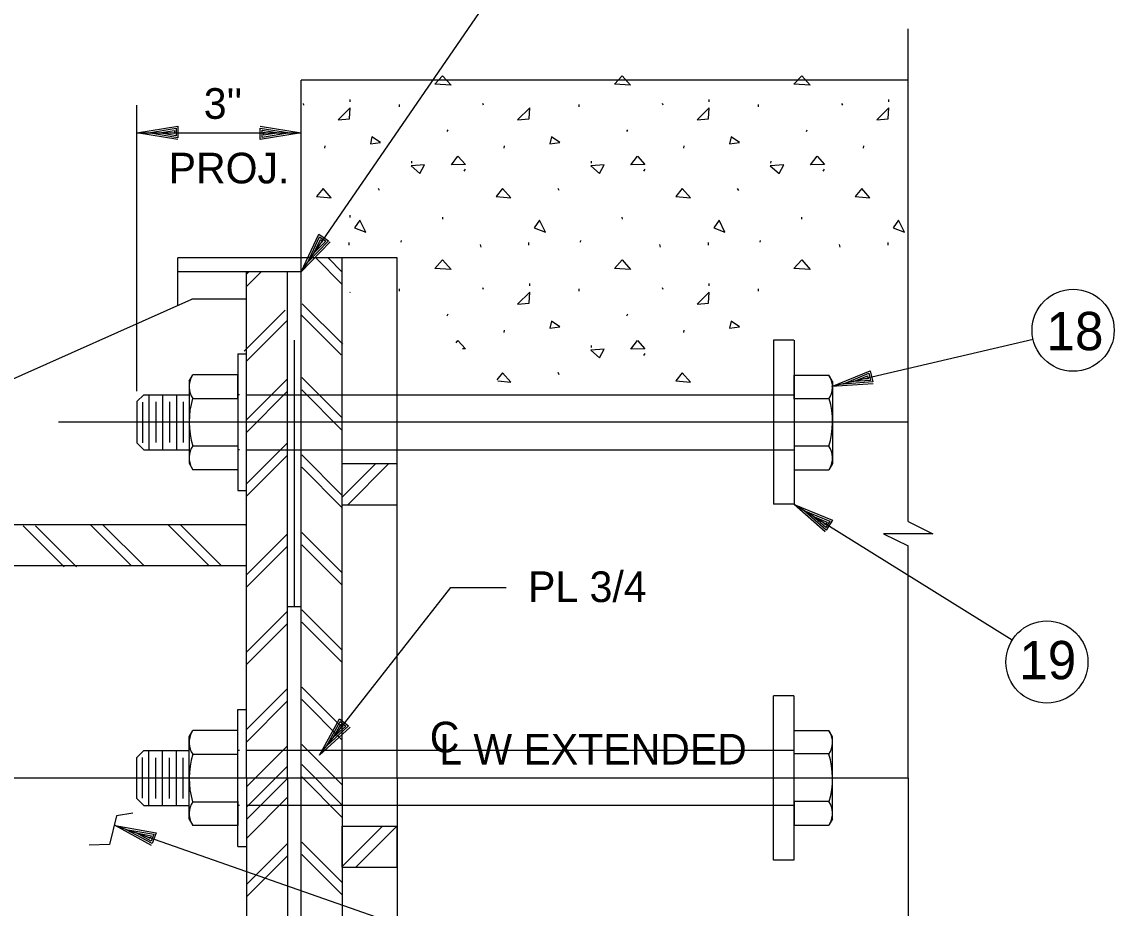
# Model space of a CAD drawing. Extents: x 0.1 to 13.5, y 0.1 to 9.5.
# Drawn here: x 8.756 to 10.418, y 6.836 to 8.186 of the extents above; entities that cross this region are included whole.
import ezdxf

# ---------------------------------------------------------------- set-up
doc = ezdxf.new("R2010")
doc.units = 0
for name, color, linetype in [('Level 10', 7, 'Continuous'), ('Level 13', 7, 'Continuous'), ('Level 2', 7, 'Continuous'), ('Level 25', 7, 'Continuous'), ('Level 3', 7, 'Continuous'), ('Level 50', 7, 'Continuous')]:
    doc.layers.add(name, color=color, linetype=linetype)

msp = doc.modelspace()

# ---------------------------------------------------------------- linework, layer by layer
at = {"layer": 'Level 10'}
for p, q in [((9.2555, 8.064), (9.2555, 8.0675)), ((9.8022, 8.064), (9.8022, 8.0675)), ((10.0755, 8.064), (10.0755, 8.0675)), ((9.1852, 8.0585), (9.1842, 8.0612)), ((9.3307, 8.056), (9.3307, 8.0597)), ((9.4585, 8.0585), (9.4575, 8.0612)), ((9.604, 8.056), (9.604, 8.0597)), ((9.7318, 8.0585), (9.7308, 8.0612)), ((9.8773, 8.056), (9.8773, 8.0597)), ((10.0052, 8.0585), (10.0041, 8.0612)), ((9.4033, 8.0185), (9.4047, 8.0214)), ((9.6766, 8.0185), (9.678, 8.0214)), ((9.9499, 8.0185), (9.9513, 8.0214)), ((9.2167, 7.9933), (9.2173, 7.9969)), ((9.49, 7.9933), (9.4906, 7.9969)), ((9.7633, 7.9933), (9.7639, 7.9969)), ((10.0367, 7.9933), (10.0372, 7.9969)), ((9.3493, 7.9705), (9.3495, 7.9732)), ((9.6226, 7.9705), (9.6228, 7.9732)), ((9.8959, 7.9705), (9.8962, 7.9732)), ((9.4291, 7.958), (9.431, 7.9611)), ((9.7024, 7.958), (9.7043, 7.9611)), ((9.9757, 7.958), (9.9776, 7.9611)), ((9.3003, 7.9287), (9.2987, 7.932)), ((9.5737, 7.9287), (9.572, 7.932)), ((9.847, 7.9287), (9.8453, 7.932)), ((9.2555, 7.8876), (9.2555, 7.8911)), ((9.3966, 7.8852), (9.3963, 7.8882)), ((9.6699, 7.8852), (9.6697, 7.8882)), ((9.9432, 7.8852), (9.943, 7.8882)), ((9.2542, 7.8457), (9.2542, 7.8494)), ((9.333, 7.8501), (9.3335, 7.8529)), ((9.5275, 7.8457), (9.5275, 7.8494)), ((9.6063, 7.8501), (9.6068, 7.8529)), ((9.8008, 7.8457), (9.8008, 7.8494)), ((9.8797, 7.8501), (9.8802, 7.8529)), ((10.0742, 7.8457), (10.0742, 7.8494)), ((9.4548, 7.8427), (9.4537, 7.8464)), ((9.7281, 7.8427), (9.727, 7.8464)), ((10.0014, 7.8427), (10.0003, 7.8464)), ((9.5288, 7.7835), (9.5288, 7.787)), ((9.8022, 7.7835), (9.8022, 7.787)), ((9.3307, 7.7754), (9.3307, 7.7792)), ((9.4585, 7.778), (9.4575, 7.7807)), ((9.604, 7.7754), (9.604, 7.7792)), ((9.7318, 7.778), (9.7308, 7.7807)), ((9.8773, 7.7754), (9.8773, 7.7792)), ((9.4033, 7.7379), (9.4047, 7.7408)), ((9.6766, 7.7379), (9.678, 7.7408)), ((9.49, 7.7127), (9.4906, 7.7163)), ((9.7633, 7.7127), (9.7639, 7.7163)), ((9.6226, 7.6899), (9.6228, 7.6927)), ((9.7024, 7.6774), (9.7043, 7.6805)), ((9.5737, 7.6482), (9.572, 7.6515))]:
    msp.add_line(p, q, dxfattribs=at)
for points in [[(9.3843, 8.0907), (9.3962, 8.1035), (9.409, 8.0893)], [(9.6577, 8.0907), (9.6695, 8.1035), (9.6823, 8.0893)], [(9.931, 8.0907), (9.9428, 8.1035), (9.9556, 8.0893)], [(9.2546, 8.038), (9.2555, 8.0547), (9.237, 8.0366)], [(9.5279, 8.038), (9.5288, 8.0547), (9.5103, 8.0366)], [(9.8012, 8.038), (9.8022, 8.0547), (9.7837, 8.0366)], [(10.0745, 8.038), (10.0755, 8.0547), (10.057, 8.0366)], [(9.2863, 7.9998), (9.3015, 8.0018), (9.2887, 8.0103)], [(9.5596, 7.9998), (9.5748, 8.0018), (9.562, 8.0103)], [(9.8329, 7.9998), (9.8481, 8.0018), (9.8353, 8.0103)], [(9.3483, 7.9664), (9.3617, 7.9545), (9.3688, 7.9678)], [(9.4095, 7.9678), (9.4195, 7.9812), (9.4308, 7.9683)], [(9.6217, 7.9664), (9.635, 7.9545), (9.6421, 7.9678)], [(9.6828, 7.9678), (9.6928, 7.9812), (9.7042, 7.9683)], [(9.895, 7.9664), (9.9083, 7.9545), (9.9154, 7.9678)], [(9.9561, 7.9678), (9.9662, 7.9812), (9.9775, 7.9683)], [(9.2267, 7.9175), (9.2143, 7.9317), (9.2043, 7.9199)], [(9.5, 7.9175), (9.4876, 7.9317), (9.4777, 7.9199)], [(9.7733, 7.9175), (9.7609, 7.9317), (9.751, 7.9199)], [(10.0466, 7.9175), (10.0342, 7.9317), (10.0243, 7.9199)], [(9.2623, 7.8719), (9.2794, 7.8653), (9.2704, 7.8837)], [(9.5357, 7.8719), (9.5527, 7.8653), (9.5437, 7.8837)], [(9.809, 7.8719), (9.826, 7.8653), (9.817, 7.8837)], [(10.0823, 7.8719), (10.0993, 7.8653), (10.0903, 7.8837)], [(9.3843, 7.8101), (9.3962, 7.823), (9.409, 7.8087)], [(9.6577, 7.8101), (9.6695, 7.823), (9.6823, 7.8087)], [(9.931, 7.8101), (9.9428, 7.823), (9.9556, 7.8087)], [(9.5279, 7.7574), (9.5288, 7.7741), (9.5103, 7.756)], [(9.8012, 7.7574), (9.8022, 7.7741), (9.7837, 7.756)], [(9.5596, 7.7193), (9.5748, 7.7212), (9.562, 7.7298)], [(9.8329, 7.7193), (9.8481, 7.7212), (9.8353, 7.7298)], [(9.6828, 7.6873), (9.6928, 7.7006), (9.7042, 7.6878)], [(9.6217, 7.6858), (9.635, 7.674), (9.6421, 7.6873)], [(9.7733, 7.6369), (9.7609, 7.6512), (9.751, 7.6393)]]:
    msp.add_lwpolyline(points, close=True, dxfattribs=at)
for points in [[(9.2555, 7.7741), (9.255, 7.7736)], [(9.2555, 7.7734), (9.2555, 7.7741)], [(9.4166, 7.6967), (9.4195, 7.7006)], [(9.4195, 7.7006), (9.4308, 7.6878)], [(9.4308, 7.6878), (9.4266, 7.6877)], [(9.4876, 7.6512), (9.4788, 7.6406)], [(9.5, 7.6369), (9.4876, 7.6512)], [(9.4805, 7.639), (9.5, 7.6369)]]:
    msp.add_lwpolyline(points, dxfattribs=at)
at = {"layer": 'Level 13'}
msp.add_lwpolyline([(10.1049, 7.425), (10.1424, 7.4064), (10.0675, 7.4064), (10.1049, 7.3877)], dxfattribs=at)
at = {"layer": 'Level 2'}
for p, q in [((10.1049, 7.425), (10.1049, 8.1749)), ((9.1809, 5.9467), (9.1809, 8.0969)), ((10.1049, 8.0969), (9.1809, 8.0969)), ((9.2434, 7.8261), (8.9934, 7.8261)), ((8.9934, 7.8052), (8.9934, 7.8261)), ((9.3268, 7.8261), (9.2434, 7.8261)), ((9.2434, 7.513), (9.2434, 7.8261)), ((9.3268, 7.513), (9.3268, 7.8261)), ((9.1809, 7.8052), (8.9934, 7.8052)), ((9.0976, 7.0344), (9.0976, 7.8052)), ((9.1601, 7.0344), (9.1601, 7.8052)), ((9.0976, 7.7636), (9.0143, 7.7636)), ((9.1705, 7.2948), (9.1705, 7.7011)), ((9.8997, 7.7011), (9.8997, 7.4511)), ((9.9309, 7.7011), (9.8997, 7.7011)), ((9.9312, 7.7011), (9.9312, 7.4511)), ((9.0846, 7.6802), (9.0846, 7.4719)), ((9.0846, 7.6802), (9.0976, 7.6802)), ((9.0104, 7.6386), (9.016, 7.6483)), ((9.0104, 7.6386), (9.0104, 7.5135)), ((9.0846, 7.6483), (9.016, 7.6483)), ((9.0846, 7.6117), (9.0846, 7.6483)), ((9.9312, 7.6113), (9.9312, 7.6479)), ((9.9312, 7.6479), (9.9841, 7.6479)), ((9.9897, 7.6382), (9.9841, 7.6479)), ((9.9897, 7.6382), (9.9897, 7.5131)), ((8.9414, 7.6179), (8.9309, 7.6074)), ((8.9414, 7.6179), (9.0104, 7.6179)), ((8.9491, 7.6179), (8.9491, 7.5342)), ((8.97, 7.6179), (8.97, 7.5342)), ((8.9909, 7.6179), (8.9909, 7.5342)), ((9.0872, 7.6179), (9.0846, 7.6179)), ((9.0976, 7.6175), (9.9312, 7.6175)), ((8.9309, 7.6074), (8.9309, 7.5447)), ((8.9309, 7.6074), (8.9309, 7.5447)), ((8.9392, 7.6068), (8.9392, 7.5446)), ((8.9595, 7.6073), (8.9595, 7.5451)), ((8.9804, 7.6073), (8.9804, 7.5451)), ((9.0013, 7.6073), (9.0013, 7.5451)), ((9.0159, 7.6122), (9.0846, 7.6122)), ((9.9843, 7.6118), (9.9312, 7.6118)), ((10.1049, 7.5761), (8.8116, 7.5761)), ((8.9414, 7.5342), (8.9309, 7.5447)), ((8.9414, 7.5342), (9.0104, 7.5342)), ((9.0159, 7.5399), (9.0846, 7.5399)), ((9.0872, 7.5342), (9.0846, 7.5342)), ((9.0976, 7.5338), (9.3268, 7.5338)), ((9.3268, 7.5338), (9.9312, 7.5338)), ((9.9843, 7.5394), (9.9312, 7.5394)), ((9.0104, 7.5135), (9.016, 7.5038)), ((9.0846, 7.5038), (9.016, 7.5038)), ((9.2434, 7.4505), (9.2434, 7.513)), ((9.2434, 7.513), (9.3268, 7.513)), ((9.3268, 7.4505), (9.3268, 7.513)), ((9.9312, 7.5034), (9.9841, 7.5034)), ((9.9897, 7.5131), (9.9841, 7.5034)), ((9.0846, 7.4719), (9.0976, 7.4719)), ((9.2434, 7.4505), (9.3268, 7.4505)), ((9.2434, 7.0344), (9.2434, 7.4505)), ((9.3268, 7.0344), (9.3268, 7.4505)), ((9.9309, 7.4511), (9.8997, 7.4511)), ((9.0976, 7.4198), (8.3684, 7.4198)), ((10.1049, 7.0344), (10.1049, 7.3877)), ((9.0976, 7.3573), (8.3684, 7.3573)), ((9.1809, 7.2948), (9.1601, 7.2948)), ((9.8997, 6.9094), (9.8997, 7.1594)), ((9.9309, 7.1594), (9.8997, 7.1594)), ((9.9312, 6.9094), (9.9312, 7.1594)), ((9.0846, 6.9302), (9.0846, 7.1386)), ((9.0846, 7.1386), (9.0976, 7.1386)), ((9.0104, 7.0969), (9.016, 7.1066)), ((9.0846, 7.1066), (9.016, 7.1066)), ((9.9312, 7.107), (9.9841, 7.107)), ((9.9897, 7.0973), (9.9841, 7.107)), ((9.0104, 6.9718), (9.0104, 7.0969)), ((9.9897, 6.9723), (9.9897, 7.0973)), ((8.9414, 7.0762), (8.9309, 7.0658)), ((8.9414, 7.0762), (9.0104, 7.0762)), ((8.9491, 6.9926), (8.9491, 7.0762)), ((8.97, 6.9926), (8.97, 7.0762)), ((8.9909, 6.9926), (8.9909, 7.0762)), ((9.0159, 7.0706), (9.0846, 7.0706)), ((9.0872, 7.0762), (9.0846, 7.0762)), ((9.0976, 7.0766), (9.3268, 7.0766)), ((9.3268, 7.0766), (9.9312, 7.0766)), ((9.9843, 7.071), (9.9312, 7.071)), ((8.9309, 7.003), (8.9309, 7.0658)), ((8.9309, 7.003), (8.9309, 7.0658)), ((8.9392, 7.0036), (8.9392, 7.0658)), ((8.9595, 7.0031), (8.9595, 7.0653)), ((8.9804, 7.0031), (8.9804, 7.0653)), ((9.0013, 7.0031), (9.0013, 7.0653)), ((10.1049, 7.0344), (8.1558, 7.0344)), ((9.0976, 7.0344), (9.0976, 6.2636)), ((9.1601, 7.0344), (9.1601, 6.2636)), ((9.2434, 7.0344), (9.2434, 6.535)), ((9.3268, 7.0344), (9.3268, 6.2427)), ((10.1049, 7.0344), (10.1049, 6.6363)), ((8.9414, 6.9926), (8.9309, 7.003)), ((8.9414, 6.9926), (9.0104, 6.9926)), ((9.0159, 6.9982), (9.0846, 6.9982)), ((9.0846, 6.9987), (9.0846, 6.9622)), ((9.0872, 6.9926), (9.0846, 6.9926)), ((9.0976, 6.993), (9.9312, 6.993)), ((9.9312, 6.9991), (9.9312, 6.9626)), ((9.9843, 6.9986), (9.9312, 6.9986)), ((9.0104, 6.9718), (9.016, 6.9622)), ((9.9897, 6.9723), (9.9841, 6.9626)), ((9.0846, 6.9622), (9.016, 6.9622)), ((9.2434, 6.8987), (9.2434, 6.9612)), ((9.3268, 6.8987), (9.3268, 6.9612)), ((9.9312, 6.9626), (9.9841, 6.9626)), ((9.0846, 6.9302), (9.0976, 6.9302)), ((9.9309, 6.9094), (9.8997, 6.9094))]:
    msp.add_line(p, q, dxfattribs=at)
for points in [[(9.2434, 7.7857), (9.2031, 7.8261)], [(9.2434, 7.8046), (9.2219, 7.8261)], [(9.0976, 7.8026), (9.1002, 7.8052)], [(9.0976, 7.7826), (9.1202, 7.8052)], [(9.0976, 7.8015), (9.1013, 7.8052)], [(9.2441, 7.695), (9.1826, 7.7565)], [(9.094, 7.684), (9.1565, 7.7465)], [(9.242, 7.6785), (9.1805, 7.74)], [(9.0976, 7.669), (9.1601, 7.7315)], [(9.0976, 7.5795), (9.1601, 7.642)], [(9.2434, 7.5825), (9.1819, 7.6441)], [(9.0976, 7.5606), (9.1601, 7.6231)], [(9.2434, 7.5637), (9.1819, 7.6252)], [(9.0976, 7.4825), (9.1601, 7.5449)], [(9.0976, 7.4636), (9.1601, 7.5261)], [(9.2434, 7.4647), (9.1819, 7.5262)], [(9.2434, 7.4458), (9.1819, 7.5074)], [(9.2434, 7.462), (9.2944, 7.513)], [(9.2518, 7.4505), (9.3143, 7.513)], [(8.8202, 7.3559), (8.7577, 7.4184)], [(8.8202, 7.3559), (8.7577, 7.4184)], [(8.8391, 7.3559), (8.7766, 7.4184)], [(8.8391, 7.3559), (8.7766, 7.4184)], [(8.9228, 7.3573), (8.8603, 7.4198)], [(8.9228, 7.3573), (8.8603, 7.4198)], [(8.9417, 7.3573), (8.8792, 7.4198)], [(8.9417, 7.3573), (8.8792, 7.4198)], [(9.0407, 7.3573), (8.9782, 7.4198)], [(9.0407, 7.3573), (8.9782, 7.4198)], [(9.0595, 7.3573), (8.997, 7.4198)], [(9.0595, 7.3573), (8.997, 7.4198)], [(9.0976, 7.4182), (9.096, 7.4198)], [(9.0976, 7.3438), (9.1601, 7.4063)], [(9.2434, 7.3468), (9.1819, 7.4084)], [(9.0976, 7.3249), (9.1601, 7.3874)], [(9.2434, 7.328), (9.1819, 7.3895)], [(9.0976, 7.2259), (9.1601, 7.2884)], [(9.2434, 7.229), (9.1819, 7.2905)], [(9.0976, 7.2071), (9.1601, 7.2696)], [(9.2434, 7.2101), (9.1819, 7.2717)], [(9.0976, 7.1081), (9.1601, 7.1706)], [(9.2434, 7.1111), (9.1819, 7.1727)], [(9.0976, 7.0892), (9.1601, 7.1517)], [(9.2434, 7.0923), (9.1819, 7.1538)], [(9.2434, 7.0239), (9.1819, 7.0854)], [(9.0976, 7.0208), (9.1601, 7.0833)], [(9.0976, 6.9902), (9.1601, 7.0527)], [(9.2434, 6.9933), (9.1819, 7.0548)], [(9.0976, 6.9714), (9.1601, 7.0339)], [(9.2434, 6.9744), (9.1819, 7.036)], [(9.0976, 6.9426), (9.1601, 7.0051)], [(9.2434, 6.8999), (9.3047, 6.9612)], [(9.2641, 6.8987), (9.3266, 6.9612)], [(9.0976, 6.8724), (9.1601, 6.9349)], [(9.2434, 6.8754), (9.1819, 6.937)], [(9.2434, 6.8566), (9.1819, 6.9181)], [(9.0976, 6.8535), (9.1601, 6.916)]]:
    msp.add_lwpolyline(points, dxfattribs=at)
for centre, radius, start, end in [((9.0417, 7.63), 0.0314, 149.7124, 214.511), ((9.9584, 7.6296), 0.0314, 325.489, 30.2876), ((9.1359, 7.5765), 0.1255, 163.5034, 196.9816), ((9.8643, 7.5761), 0.1255, 343.0184, 16.4966), ((9.0417, 7.5221), 0.0314, 145.489, 210.2876), ((9.9584, 7.5217), 0.0314, 329.7124, 34.511), ((9.0417, 7.0883), 0.0314, 149.7124, 214.511), ((9.9584, 7.0887), 0.0314, 325.489, 30.2876), ((9.1359, 7.0339), 0.1255, 163.0184, 196.4966), ((9.8643, 7.0343), 0.1255, 343.5034, 16.9816), ((9.0417, 6.9804), 0.0314, 145.489, 210.2876), ((9.9584, 6.9809), 0.0314, 329.7124, 34.511)]:
    msp.add_arc(centre, radius, start, end, dxfattribs=at)
at = {"layer": 'Level 25'}
for p, q in [((9.1809, 7.8052), (9.4696, 8.2251)), ((8.9934, 7.7543), (8.9934, 7.8052)), ((8.4309, 7.5031), (9.0143, 7.7636)), ((8.8997, 6.9771), (8.889, 6.9333)), ((8.9246, 6.9807), (8.8997, 6.9771)), ((9.2434, 6.9612), (9.3268, 6.9612)), ((8.889, 6.9333), (8.8582, 6.9321)), ((9.2434, 6.8987), (9.3268, 6.8987))]:
    msp.add_line(p, q, dxfattribs=at)
at = {"layer": 'Level 3'}
for p, q in [((8.9309, 7.6235), (8.9309, 8.0586)), ((8.9309, 8.0165), (9.1809, 8.0165)), ((8.9309, 8.0165), (8.9309, 8.0165)), ((8.9483, 8.0165), (8.9483, 8.0165)), ((9.1636, 8.0165), (9.1636, 8.0165)), ((9.1809, 8.0165), (9.1809, 8.0165)), ((10.2951, 7.7018), (9.9885, 7.6303)), ((10.0054, 7.6342), (10.0054, 7.6342)), ((9.9885, 7.6303), (9.9885, 7.6303)), ((10.2631, 7.2441), (9.9312, 7.451)), ((9.2089, 7.0691), (9.4087, 7.3246)), ((9.4087, 7.3246), (9.4932, 7.3246)), ((9.2089, 7.0691), (9.2089, 7.0691)), ((9.2195, 7.0828), (9.2195, 7.0828)), ((8.8977, 6.962), (9.4046, 6.7848)), ((8.8977, 6.962), (8.8977, 6.962)), ((8.9141, 6.9563), (8.9141, 6.9563))]:
    msp.add_line(p, q, dxfattribs=at)
for points in [[(8.9933, 8.0062), (8.9309, 8.0165), (8.9933, 8.0268), (8.9933, 8.0092), (8.9483, 8.0165), (8.9906, 8.0235), (8.9906, 8.0122), (8.9649, 8.0165), (8.9879, 8.0202), (8.9879, 8.0155), (8.9823, 8.0165)], [(9.1186, 8.0268), (9.1809, 8.0165), (9.1186, 8.0062), (9.1186, 8.0238), (9.1636, 8.0165), (9.1213, 8.0095), (9.1213, 8.0208), (9.1469, 8.0165), (9.1239, 8.0128), (9.1239, 8.0175), (9.1296, 8.0165)], [(10.0516, 7.6344), (9.9885, 7.6303), (10.0469, 7.6545), (10.0509, 7.6373), (10.0054, 7.6342), (10.045, 7.6506), (10.0476, 7.6396), (10.0216, 7.638), (10.0432, 7.6468), (10.0442, 7.6422), (10.0385, 7.6419)], [(9.2554, 7.1118), (9.2089, 7.0691), (9.2391, 7.1246), (9.253, 7.1137), (9.2195, 7.0828), (9.2401, 7.1204), (9.249, 7.1134), (9.2298, 7.0959), (9.2411, 7.1163), (9.2448, 7.1134), (9.2405, 7.1095)], [(8.9532, 6.9316), (8.8977, 6.962), (8.96, 6.9512), (8.9542, 6.9345), (8.9141, 6.9563), (8.9564, 6.9489), (8.9526, 6.9382), (8.9298, 6.9508), (8.9528, 6.9466), (8.9512, 6.9422), (8.9462, 6.945)]]:
    msp.add_lwpolyline(points, dxfattribs=at)
for centre in [(10.356, 7.7161), (10.3161, 7.211)]:
    msp.add_circle(centre, 0.0625, dxfattribs=at)
at = {"layer": 'Level 50'}
for p, q in [((9.1908, 7.8195), (9.1908, 7.8195)), ((9.1809, 7.8052), (9.1809, 7.8052)), ((9.9312, 7.451), (9.9312, 7.451)), ((9.9459, 7.4419), (9.9459, 7.4419))]:
    msp.add_line(p, q, dxfattribs=at)
for points in [[(9.2248, 7.8507), (9.1809, 7.8052), (9.2077, 7.8624), (9.2223, 7.8524), (9.1908, 7.8195), (9.209, 7.8583), (9.2183, 7.8519), (9.2002, 7.8332), (9.2102, 7.8543), (9.2141, 7.8516), (9.21, 7.8475)], [(9.9786, 7.4093), (9.9312, 7.451), (9.9896, 7.4268), (9.9802, 7.4118), (9.9459, 7.4419), (9.9855, 7.4254), (9.9795, 7.4158), (9.96, 7.4331), (9.9815, 7.424), (9.979, 7.42), (9.9748, 7.4239)]]:
    msp.add_lwpolyline(points, dxfattribs=at)

# ---------------------------------------------------------------- texts
at = {"layer": 'Level 3'}
for s, height, p in [("3''", 0.04667, (9.0326, 8.0379)), ('PROJ.', 0.04667, (8.9792, 7.9396)), ('18', 0.05833, (10.3154, 7.6857)), ('PL 3/4', 0.04667, (9.5263, 7.3023)), ('19', 0.05833, (10.274, 7.1848)), ('C', 0.0467, (9.3767, 7.0734)), ('L W EXTENDED', 0.046667, (9.3911, 7.055))]:
    msp.add_text(s, height=height, dxfattribs=at).set_placement(p)

doc.saveas('drawing.dxf')
